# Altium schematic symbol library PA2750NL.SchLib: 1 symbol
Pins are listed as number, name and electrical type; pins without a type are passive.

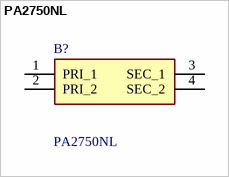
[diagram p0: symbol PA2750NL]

## PA2750NL
designator B?
Common Mode Chokes / Filters 9.4mOhms 400uH 6A SMD Toroid Choke; Manufacturer_Name: PULSE; Geometry.Height: 10mm
footprint PA2750NL
pins: 1 PRI_1, 2 PRI_2, 3 SEC_1, 4 SEC_2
